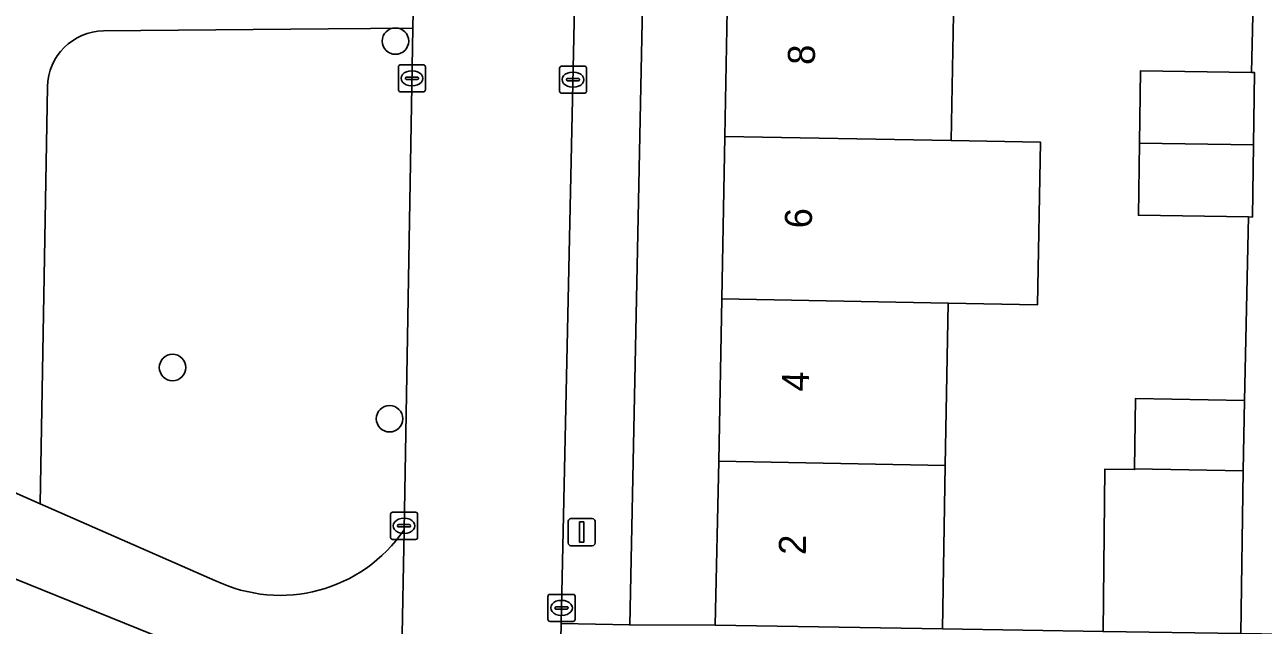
# Model space of a CAD drawing. Extents: x 160023 to 161302, y 384750 to 385707.
# Drawn here: x 160601.98 to 160647.75, y 385046.66 to 385068.83 of the extents above; entities that cross this region are included whole.
import ezdxf

# ---------------------------------------------------------------- set-up
doc = ezdxf.new("R2010")
doc.units = 0
for name, color, linetype in [('IMGEO_Boom', 7, 'Continuous'), ('IMGEO_Erf', 7, 'Continuous'), ('IMGEO_Groenvoorziening', 7, 'Continuous'), ('IMGEO_Kolk', 7, 'Continuous'), ('IMGEO_Lichtmast', 7, 'Continuous'), ('IMGEO_Pand', 7, 'Continuous'), ('IMGEO_Pand_nummerreeks', 7, 'Continuous'), ('IMGEO_Rijbaan_lokaal_gesloten', 7, 'Continuous'), ('IMGEO_Rijbaan_lokaal_open', 7, 'Continuous'), ('IMGEO_Voetpad_halfverhard', 7, 'Continuous'), ('IMGEO_Voetpad_open', 7, 'Continuous')]:
    doc.layers.add(name, color=color, linetype=linetype)

msp = doc.modelspace()

# ---------------------------------------------------------------- linework, layer by layer
at = {"layer": 'IMGEO_Boom'}
for centre in [(160615.678, 385068.228), (160607.438, 385056.173), (160615.459, 385054.281)]:
    msp.add_circle(centre, 0.489, dxfattribs=at)
at = {"layer": 'IMGEO_Erf'}
msp.add_lwpolyline([(160628.07, 385076.698), (160628.181, 385082.695), (160628.291, 385088.692), (160628.402, 385094.689), (160628.515, 385100.842), (160625.445, 385100.857), (160624.337, 385046.664), (160627.498, 385046.657), (160627.628, 385052.71), (160627.739, 385058.707), (160627.849, 385064.704), (160627.96, 385070.701)], close=True, dxfattribs=at)
msp.add_lwpolyline([(160636.335, 385070.547), (160636.224, 385064.55), (160639.522, 385064.489), (160639.412, 385058.492), (160636.114, 385058.553), (160636.003, 385052.556), (160635.899, 385046.526), (160641.833, 385046.422), (160641.899, 385052.417), (160643.001, 385052.403), (160643.001, 385052.427), (160643.034, 385055.029), (160647.056, 385054.955), (160647.208, 385061.732), (160643.139, 385061.793), (160643.179, 385064.461), (160643.219, 385067.129), (160647.327, 385067.068), (160647.48, 385073.914)], dxfattribs=at)
at = {"layer": 'IMGEO_Groenvoorziening'}
for points in [[(160616.32, 385068.707), (160613.186, 385068.678), (160604.892, 385068.6)], [(160615.997, 385050.184), (160616.32, 385068.707)], [(160602.812, 385066.535), (160602.546, 385051.141), (160609.007, 385048.313)]]:
    msp.add_lwpolyline(points, dxfattribs=at)
for centre, radius, start, end in [((160604.912, 385066.5), 2.1, 90.5479, 179.0374), ((160611.42, 385053.291), 5.532, 244.142, 325.828)]:
    msp.add_arc(centre, radius, start, end, dxfattribs=at)
at = {"layer": 'IMGEO_Kolk'}
for p, q in [((160615.786, 385066.425), (160615.786, 385067.277)), ((160615.861, 385067.351), (160616.713, 385067.351)), ((160616.274, 385067.131), (160616.299, 385067.131)), ((160616.787, 385067.277), (160616.787, 385066.425)), ((160621.741, 385066.376), (160621.741, 385067.228)), ((160621.816, 385067.302), (160622.668, 385067.302)), ((160622.229, 385067.082), (160622.254, 385067.082)), ((160622.742, 385067.228), (160622.742, 385066.376)), ((160616.045, 385066.845), (160616.045, 385066.857)), ((160616.483, 385066.808), (160616.085, 385066.808)), ((160616.088, 385066.894), (160616.486, 385066.894)), ((160616.529, 385066.857), (160616.529, 385066.845)), ((160622, 385066.796), (160622, 385066.808)), ((160622.438, 385066.759), (160622.04, 385066.759)), ((160622.043, 385066.845), (160622.441, 385066.845)), ((160622.484, 385066.808), (160622.484, 385066.796)), ((160616.713, 385066.351), (160615.861, 385066.351)), ((160616.297, 385066.571), (160616.272, 385066.571)), ((160622.668, 385066.302), (160621.816, 385066.302)), ((160622.252, 385066.522), (160622.227, 385066.522)), ((160615.497, 385049.9), (160615.497, 385050.752)), ((160615.572, 385050.826), (160616.424, 385050.826)), ((160615.985, 385050.606), (160616.01, 385050.606)), ((160616.498, 385050.752), (160616.498, 385049.9)), ((160615.756, 385050.32), (160615.756, 385050.332)), ((160616.194, 385050.283), (160615.796, 385050.283)), ((160615.799, 385050.369), (160616.197, 385050.369)), ((160616.24, 385050.332), (160616.24, 385050.32)), ((160616.424, 385049.826), (160615.572, 385049.826)), ((160616.008, 385050.046), (160615.983, 385050.046)), ((160621.316, 385046.869), (160621.316, 385047.721)), ((160621.391, 385047.795), (160622.243, 385047.795)), ((160621.804, 385047.575), (160621.829, 385047.575)), ((160622.317, 385047.721), (160622.317, 385046.869)), ((160621.575, 385047.289), (160621.575, 385047.301)), ((160622.013, 385047.252), (160621.615, 385047.252)), ((160621.618, 385047.338), (160622.016, 385047.338)), ((160621.827, 385047.015), (160621.802, 385047.015)), ((160622.059, 385047.301), (160622.059, 385047.289)), ((160622.243, 385046.795), (160621.391, 385046.795))]:
    msp.add_line(p, q, dxfattribs=at)
for points in [[(160615.786, 385066.425), (160615.786, 385067.277)], [(160615.861, 385067.351), (160616.713, 385067.351)], [(160616.787, 385067.277), (160616.787, 385066.425)], [(160621.741, 385066.376), (160621.741, 385067.228)], [(160621.816, 385067.302), (160622.668, 385067.302)], [(160622.742, 385067.228), (160622.742, 385066.376)], [(160616.713, 385066.351), (160615.861, 385066.351)], [(160622.668, 385066.302), (160621.816, 385066.302)], [(160615.497, 385049.9), (160615.497, 385050.752)], [(160615.572, 385050.826), (160616.424, 385050.826)], [(160616.498, 385050.752), (160616.498, 385049.9)], [(160616.424, 385049.826), (160615.572, 385049.826)], [(160621.316, 385046.869), (160621.316, 385047.721)], [(160621.391, 385047.795), (160622.243, 385047.795)], [(160622.317, 385047.721), (160622.317, 385046.869)], [(160622.243, 385046.795), (160621.391, 385046.795)]]:
    msp.add_lwpolyline(points, dxfattribs=at)
for centre, radius, start, end in [((160615.863, 385067.275), 0.0765, 91.552, 178.448), ((160615.863, 385067.275), 0.0765, 91.552, 178.448), ((160616.711, 385067.275), 0.0765, 1.552, 88.448), ((160616.711, 385067.275), 0.0765, 1.552, 88.448), ((160621.818, 385067.226), 0.0765, 91.552, 178.448), ((160621.818, 385067.226), 0.0765, 91.552, 178.448), ((160622.666, 385067.226), 0.0765, 1.552, 88.448), ((160622.666, 385067.226), 0.0765, 1.552, 88.448), ((160616.085, 385066.854), 0.0403, 85.8775, 175.7526), ((160616.082, 385066.844), 0.0366, 178.938, 274.7102), ((160616.486, 385066.851), 0.043, 264.8664, 352.4533), ((160616.49, 385066.856), 0.0386, 1.7309, 96.639), ((160622.04, 385066.805), 0.0403, 85.8775, 175.7526), ((160622.037, 385066.795), 0.0366, 178.938, 274.7102), ((160622.441, 385066.802), 0.043, 264.8664, 352.4533), ((160622.445, 385066.807), 0.0386, 1.7309, 96.639), ((160615.863, 385066.427), 0.0765, 181.552, 268.448), ((160615.863, 385066.427), 0.0765, 181.552, 268.448), ((160616.711, 385066.427), 0.0765, 271.552, 358.448), ((160616.711, 385066.427), 0.0765, 271.552, 358.448), ((160621.818, 385066.378), 0.0765, 181.552, 268.448), ((160621.818, 385066.378), 0.0765, 181.552, 268.448), ((160622.666, 385066.378), 0.0765, 271.552, 358.448), ((160622.666, 385066.378), 0.0765, 271.552, 358.448), ((160615.574, 385050.75), 0.0765, 91.552, 178.448), ((160615.574, 385050.75), 0.0765, 91.552, 178.448), ((160616.422, 385050.75), 0.0765, 1.552, 88.448), ((160616.422, 385050.75), 0.0765, 1.552, 88.448), ((160615.796, 385050.329), 0.0403, 85.8775, 175.7526), ((160615.793, 385050.319), 0.0366, 178.938, 274.7102), ((160616.197, 385050.326), 0.043, 264.8664, 352.4533), ((160616.201, 385050.331), 0.0386, 1.7309, 96.639), ((160615.574, 385049.902), 0.0765, 181.552, 268.448), ((160615.574, 385049.902), 0.0765, 181.552, 268.448), ((160616.422, 385049.902), 0.0765, 271.552, 358.448), ((160616.422, 385049.902), 0.0765, 271.552, 358.448), ((160621.393, 385047.719), 0.0765, 91.552, 178.448), ((160621.393, 385047.719), 0.0765, 91.552, 178.448), ((160622.241, 385047.719), 0.0765, 1.552, 88.448), ((160622.241, 385047.719), 0.0765, 1.552, 88.448), ((160621.615, 385047.298), 0.0403, 85.8775, 175.7526), ((160621.612, 385047.288), 0.0366, 178.938, 274.7102), ((160622.016, 385047.295), 0.043, 264.8664, 352.4533), ((160622.02, 385047.3), 0.0386, 1.7309, 96.639), ((160621.393, 385046.871), 0.0765, 181.552, 268.448), ((160621.393, 385046.871), 0.0765, 181.552, 268.448), ((160622.241, 385046.871), 0.0765, 271.552, 358.448), ((160622.241, 385046.871), 0.0765, 271.552, 358.448)]:
    msp.add_arc(centre, radius, start, end, dxfattribs=at)
for centre, major_axis, ratio, start_param, end_param in [((160616.273, 385066.851), (-0.387, 0.002), 0.722429, 4.712389, 7.853982), ((160616.298, 385066.851), (-0.39, 0.002), 0.717154, 1.570796, 4.712389), ((160622.228, 385066.802), (-0.387, 0.002), 0.722429, 4.712389, 7.853982), ((160622.253, 385066.802), (-0.39, 0.002), 0.717154, 1.570796, 4.712389), ((160615.984, 385050.326), (-0.387, 0.002), 0.722429, 4.712389, 7.853982), ((160616.009, 385050.326), (-0.39, 0.002), 0.717154, 1.570796, 4.712389), ((160621.803, 385047.295), (-0.387, 0.002), 0.722429, 4.712389, 7.853982), ((160621.828, 385047.295), (-0.39, 0.002), 0.717154, 1.570796, 4.712389)]:
    msp.add_ellipse(centre, major_axis=major_axis, ratio=ratio, start_param=start_param, end_param=end_param, dxfattribs=at)
at = {"layer": 'IMGEO_Lichtmast'}
for p, q in [((160622.065, 385049.693), (160622.065, 385050.493)), ((160622.065, 385050.493), (160622.065, 385049.693)), ((160622.165, 385050.593), (160622.955, 385050.593)), ((160622.955, 385050.593), (160622.165, 385050.593)), ((160623.055, 385050.493), (160623.055, 385049.693)), ((160623.055, 385049.693), (160623.055, 385050.493)), ((160622.955, 385049.593), (160622.165, 385049.593)), ((160622.165, 385049.593), (160622.955, 385049.593))]:
    msp.add_line(p, q, dxfattribs=at)
msp.add_lwpolyline([(160622.485, 385050.468), (160622.635, 385050.468), (160622.635, 385049.718), (160622.485, 385049.718), (160622.485, 385050.468)], dxfattribs=at)
for centre, start, end in [((160622.165, 385050.493), 90, 180), ((160622.165, 385050.493), 90, 180), ((160622.955, 385050.493), 0, 90), ((160622.955, 385050.493), 360, 90), ((160622.165, 385049.693), 180, 270), ((160622.165, 385049.693), 180, 270), ((160622.955, 385049.693), 270, 0), ((160622.955, 385049.693), 270, 0)]:
    msp.add_arc(centre, 0.1, start, end, dxfattribs=at)
at = {"layer": 'IMGEO_Pand'}
for points in [[(160636.224, 385064.55), (160636.335, 385070.547), (160627.96, 385070.701), (160627.849, 385064.704)], [(160647.434, 385067.066), (160647.327, 385067.068), (160643.219, 385067.129), (160643.179, 385064.461), (160647.394, 385064.398)], [(160636.114, 385058.553), (160639.412, 385058.492), (160639.522, 385064.489), (160636.224, 385064.55), (160627.849, 385064.704), (160627.739, 385058.707)], [(160647.394, 385064.398), (160643.179, 385064.461), (160643.139, 385061.793), (160647.208, 385061.732), (160647.354, 385061.73)], [(160627.739, 385058.707), (160627.628, 385052.71), (160636.003, 385052.556), (160636.114, 385058.553)], [(160647.008, 385052.354), (160647.056, 385054.955), (160643.034, 385055.029), (160643.001, 385052.427)], [(160636.003, 385052.556), (160627.628, 385052.71), (160627.498, 385046.657), (160635.899, 385046.526)], [(160647.008, 385052.354), (160643.001, 385052.427), (160643.001, 385052.403), (160641.899, 385052.417), (160641.833, 385046.422), (160646.931, 385046.352)]]:
    msp.add_lwpolyline(points, close=True, dxfattribs=at)
at = {"layer": 'IMGEO_Rijbaan_lokaal_gesloten'}
msp.add_lwpolyline([(160596.698, 385043.67), (160620.694, 385033.909), (160638.453, 385026.712), (160665.07, 385015.82), (160667.501, 385021.654), (160664.82, 385022.747), (160662.491, 385023.66), (160645.566, 385030.496), (160642.12, 385031.906), (160624.532, 385039.041), (160612.845, 385043.826), (160590.309, 385052.935)], dxfattribs=at)
at = {"layer": 'IMGEO_Rijbaan_lokaal_open'}
msp.add_lwpolyline([(160622.916, 385099.184), (160622.965, 385101.188), (160623.082, 385106.004), (160623.722, 385132.207), (160617.844, 385132.455), (160617.723, 385128.133), (160617.484, 385119.568), (160617.43, 385117.621), (160617.044, 385103.79), (160616.494, 385078.673), (160616.352, 385070.534), (160616.32, 385068.707), (160615.997, 385050.184), (160615.918, 385045.67), (160621.727, 385043.212), (160621.803, 385046.719), (160622.325, 385070.649)], close=True, dxfattribs=at)
at = {"layer": 'IMGEO_Voetpad_halfverhard'}
for points in [[(160604.892, 385068.6), (160613.186, 385068.678), (160616.32, 385068.707), (160616.352, 385070.534), (160613.21, 385070.504), (160604.827, 385070.424)], [(160600.625, 385066.818), (160600.581, 385064.559), (160600.531, 385061.772), (160600.419, 385052.076), (160602.546, 385051.141), (160602.812, 385066.535)]]:
    msp.add_lwpolyline(points, dxfattribs=at)
msp.add_arc((160604.912, 385066.5), 2.1, 90.5479, 179.0374, dxfattribs=at)
at = {"layer": 'IMGEO_Voetpad_open'}
msp.add_lwpolyline([(160625.445, 385100.857), (160625.449, 385101.157), (160622.965, 385101.188), (160622.916, 385099.184), (160622.325, 385070.649), (160621.803, 385046.719), (160624.337, 385046.664)], close=True, dxfattribs=at)
for points in [[(160647.48, 385073.914), (160647.327, 385067.068), (160647.434, 385067.066), (160647.394, 385064.398), (160647.354, 385061.73), (160647.208, 385061.732), (160647.056, 385054.955), (160647.008, 385052.354), (160646.931, 385046.352), (160648.462, 385046.325), (160648.513, 385049.638), (160648.609, 385055.113), (160648.401, 385055.116), (160648.447, 385058.252), (160648.491, 385061.303), (160648.717, 385061.294), (160648.767, 385064.484), (160648.82, 385067.219), (160648.52, 385067.231), (160648.64, 385070.344)], [(160609.007, 385048.313), (160602.546, 385051.141), (160600.419, 385052.076), (160593.75, 385055.007), (160581.284, 385059.577), (160573.995, 385061.918), (160565.412, 385064.24)], [(160590.309, 385052.935), (160612.845, 385043.826), (160613.259, 385044.754), (160624.936, 385040.01), (160624.532, 385039.041), (160642.12, 385031.906), (160645.566, 385030.496), (160662.491, 385023.66), (160664.82, 385022.747), (160667.501, 385021.654), (160672.047, 385019.862), (160674.225, 385018.942), (160674.322, 385022.108), (160666.556, 385025.321), (160659.482, 385028.18), (160656.701, 385029.304), (160648.029, 385032.808), (160643.261, 385034.732), (160635.524, 385037.858), (160625.737, 385041.812)], [(160625.737, 385041.812), (160621.727, 385043.212), (160615.918, 385045.67), (160615.997, 385050.184)], [(160648.211, 385043.193), (160670.9, 385042.842), (160670.994, 385045.891), (160668.145, 385045.984), (160660.638, 385046.111), (160651.64, 385046.269), (160648.462, 385046.325), (160646.931, 385046.352), (160641.833, 385046.422), (160635.899, 385046.526), (160627.498, 385046.657), (160624.337, 385046.664), (160621.803, 385046.719), (160621.727, 385043.212), (160625.737, 385041.812)]]:
    msp.add_lwpolyline(points, dxfattribs=at)
msp.add_arc((160611.42, 385053.291), 5.532, 244.142, 325.828, dxfattribs=at)

# ---------------------------------------------------------------- texts
at = {"layer": 'IMGEO_Pand_nummerreeks'}
for s, rotation, p in [('8', 88.9445, (160631.178, 385067.342)), ('6', 88.9445, (160631.067, 385061.307)), ('4', 88.9445, (160630.956, 385055.277)), ('2', 88.946, (160630.845, 385049.245))]:
    msp.add_text(s, height=1, rotation=rotation, dxfattribs=at).set_placement(p)

doc.saveas('drawing.dxf')
